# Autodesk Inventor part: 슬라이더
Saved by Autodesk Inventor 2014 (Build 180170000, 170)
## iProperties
Created: 2026-06
Part Number: 슬라이더
Material: 강철, 탄소
Document SubType Name: Modeling
Designer: dg
Density: 7.87 g/cm^3
Appearance: 반연마
Mass: 67.2554 g
Surface Area: 33.0196 cm^2
Volume: 8.54579 cm^3
Author: jhkim
Creation Date: 2026-05-29
Sending System: Autodesk Inventor 2027
Preprocessor: ST-DEVELOPER v20.1
Author: dg
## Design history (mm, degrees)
node "슬라이더1"
node "솔리드1"
node "기준1"
